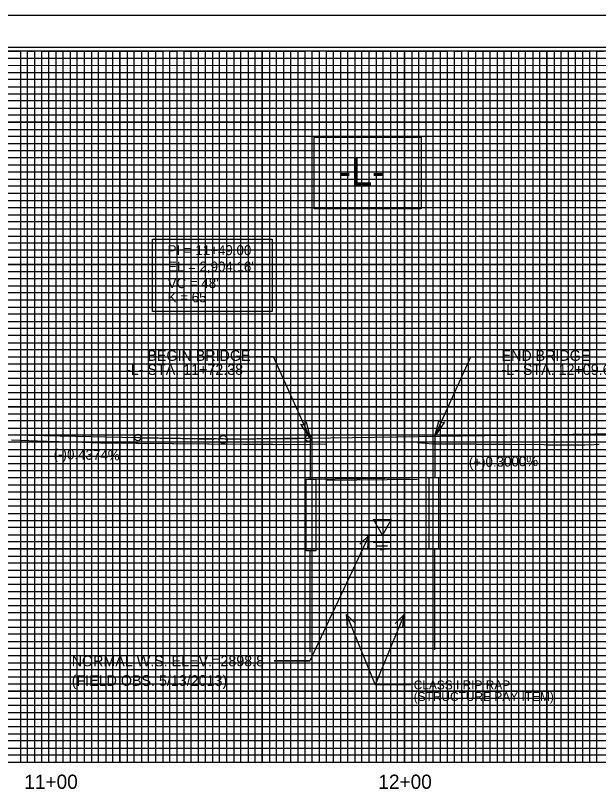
# Model space of a CAD drawing. Extents: x 1191114 to 1192543, y 893004 to 894332.
# Drawn here: x 1191383 to 1191546.9, y 894113.5 to 894332.3 of the extents above; entities that cross this region are included whole.
import ezdxf

# ---------------------------------------------------------------- set-up
doc = ezdxf.new("R2010")
doc.units = 0
for name, color, linetype in [('Default', 7, 'Continuous'), ('Exist Profile Cell', 7, 'Continuous'), ('Exist Vertical Profile Ground Line', 7, 'Continuous'), ('Prop Grid Mask', 7, 'Continuous'), ('Prop PFL Text', 7, 'Continuous'), ('Prop Roadway Bridge', 7, 'Continuous'), ('Prop Terminator CELL', 7, 'Continuous'), ('Prop Vertical Profile Curve Label', 7, 'Continuous'), ('Prop Vertical Profile Grade', 7, 'Continuous'), ('Prop Vertical Profile Grade Label', 7, 'Continuous'), ('Prop VPI Label', 7, 'Continuous'), ('Sheet Cutting Line CELL', 7, 'Continuous'), ('Sheet DOT Grid CELL', 7, 'Continuous'), ('Sheet Layout Profile Border Port 1', 7, 'Continuous'), ('Sheet Plot Border Inside CELL', 7, 'Continuous'), ('Sheet Plot Border Outside CELL', 7, 'Continuous'), ('Sheet Profile CELL', 7, 'Continuous'), ('Sheet Profile Grid Major CELL', 7, 'Continuous'), ('Sheet Profile Grid Middle CELL', 7, 'Continuous'), ('Sheet Profile Grid Minor CELL', 7, 'Continuous'), ('Typical Terminator CELL', 7, 'Continuous')]:
    doc.layers.add(name, color=color, linetype=linetype)

# ---------------------------------------------------------------- blocks, each defined once
blk = doc.blocks.new('Terminator Open Line')
at = {"layer": 'Default'}
blk.add_line((-9, -3.25), (0, 0), dxfattribs=at)
at = {"layer": 'Prop Terminator CELL'}
blk.add_line((-9, 3.3), (0, 0), dxfattribs=at)
blk = doc.blocks.new('TERMINATOR')
at = {"layer": 'Typical Terminator CELL'}
blk.add_lwpolyline([(-0.469, 0.081), (0, 0), (-0.471, -0.083), (-0.411, 0)], close=True, dxfattribs=at)

msp = doc.modelspace()

# ---------------------------------------------------------------- linework, layer by layer
at = {"layer": 'Default'}
for p, q in [((1191470.41, 894201.65), (1191496.05, 894201.95)), ((1191455.77, 894150.79), (1191465.77, 894150.79))]:
    msp.add_line(p, q, dxfattribs=at)
at = {"layer": 'Exist Profile Cell'}
msp.add_line((1191292.39, 894142.3), (1191713, 894142.3), dxfattribs=at)
at = {"layer": 'Exist Vertical Profile Ground Line'}
for points in [[(1191381.86, 894212.98), (1191391.62, 894212.64), (1191391.94, 894212.63), (1191401.84, 894212.28), (1191407.01, 894212.1), (1191407.45, 894212.11), (1191417.01, 894212.02), (1191417.49, 894212.03), (1191427.01, 894211.94), (1191427.53, 894211.95), (1191437.01, 894211.86), (1191437.57, 894211.87), (1191447.01, 894211.79), (1191447.46, 894211.8), (1191454.68, 894211.73), (1191455.32, 894211.74), (1191464.69, 894211.7), (1191466, 894211.74), (1191470.41, 894211.9)], [(1191496.05, 894212.2), (1191500.35, 894211.87), (1191501.99, 894211.9), (1191502.64, 894211.89), (1191511.99, 894211.81), (1191512.64, 894211.8), (1191522.18, 894211.72), (1191531.57, 894211.64), (1191532.17, 894211.62), (1191541.59, 894211.55), (1191542.16, 894211.53), (1191543, 894211.57), (1191545.63, 894211.7), (1191547.04, 894211.77)]]:
    msp.add_lwpolyline(points, dxfattribs=at)
at = {"layer": 'Prop Grid Mask'}
for points in [[(1191467.01, 894298.14), (1191497, 894298.14), (1191497, 894277.95), (1191467.01, 894277.95)], [(1191421.55, 894269.43), (1191455.19, 894269.43), (1191455.19, 894249.11), (1191421.55, 894249.11)]]:
    msp.add_lwpolyline(points, close=True, dxfattribs=at)
at = {"layer": 'Prop PFL Text'}
for p, q in [((1191455.57, 894236.32), (1191450.36, 894236.32)), ((1191465.89, 894213.45), (1191455.57, 894236.32)), ((1191500.89, 894213.98), (1191511.04, 894236.32)), ((1191511.04, 894236.32), (1191516.26, 894236.32)), ((1191482.4, 894186.2), (1191465.77, 894150.79)), ((1191481.44, 894186.2), (1191489.86, 894186.2)), ((1191483.56, 894184.17), (1191488.56, 894184.17)), ((1191484.56, 894183.17), (1191487.56, 894183.17)), ((1191485.56, 894182.17), (1191486.56, 894182.17)), ((1191476.05, 894163.83), (1191484.15, 894144.06)), ((1191492.25, 894163.83), (1191484.15, 894144.06)), ((1191465.77, 894150.79), (1191455.77, 894150.79)), ((1191494.15, 894144.06), (1191484.15, 894144.06))]:
    msp.add_line(p, q, dxfattribs=at)
msp.add_lwpolyline([(1191483.63, 894190.54), (1191488.63, 894190.54), (1191486.13, 894186.2)], close=True, dxfattribs=at)
at = {"layer": 'Prop Roadway Bridge'}
for p, q in [((1191465.89, 894213.45), (1191465.89, 894201.8)), ((1191500.89, 894213.98), (1191500.89, 894202.33)), ((1191467.49, 894201.83), (1191464.74, 894201.78)), ((1191464.74, 894181.78), (1191464.74, 894201.78)), ((1191500.89, 894202.33), (1191465.89, 894201.8)), ((1191467.49, 894181.78), (1191467.49, 894201.83)), ((1191502.04, 894202.34), (1191499.29, 894202.3)), ((1191499.29, 894182.35), (1191499.29, 894202.3)), ((1191502.04, 894182.35), (1191502.04, 894202.34)), ((1191499.29, 894182.35), (1191502.04, 894182.35)), ((1191500.89, 894153.88), (1191500.89, 894182.35)), ((1191467.49, 894181.78), (1191464.74, 894181.78)), ((1191465.89, 894153.23), (1191465.89, 894181.78))]:
    msp.add_line(p, q, dxfattribs=at)
at = {"layer": 'Prop Vertical Profile Curve Label'}
for centre in [(1191417.39, 894213.61), (1191465.39, 894213.44)]:
    msp.add_circle(centre, 0.9, dxfattribs=at)
at = {"layer": 'Prop Vertical Profile Grade'}
for p, q in [((1191342.39, 894215.25), (1191417.39, 894213.61)), ((1191465.39, 894213.44), (1191602.39, 894215.5))]:
    msp.add_line(p, q, dxfattribs=at)
msp.add_spline([(1191417.39, 894213.61), (1191418.35, 894213.59), (1191419.31, 894213.57), (1191420.27, 894213.55), (1191421.23, 894213.53), (1191422.19, 894213.51), (1191423.15, 894213.5), (1191424.11, 894213.48), (1191425.07, 894213.46), (1191426.03, 894213.45), (1191426.99, 894213.43), (1191427.95, 894213.42), (1191428.91, 894213.41), (1191429.87, 894213.4), (1191430.83, 894213.38), (1191431.79, 894213.37), (1191432.75, 894213.36), (1191433.71, 894213.35), (1191434.67, 894213.35), (1191435.63, 894213.34), (1191436.59, 894213.33), (1191437.55, 894213.32), (1191438.51, 894213.32), (1191439.47, 894213.31), (1191440.43, 894213.31), (1191441.39, 894213.31), (1191442.35, 894213.3), (1191443.31, 894213.3), (1191444.27, 894213.3), (1191445.23, 894213.3), (1191446.19, 894213.3), (1191447.15, 894213.3), (1191448.11, 894213.3), (1191449.07, 894213.3), (1191450.03, 894213.3), (1191450.99, 894213.31), (1191451.95, 894213.31), (1191452.91, 894213.32), (1191453.87, 894213.32), (1191454.83, 894213.33), (1191455.79, 894213.34), (1191456.75, 894213.34), (1191457.71, 894213.35), (1191458.67, 894213.36), (1191459.63, 894213.37), (1191460.59, 894213.38), (1191461.55, 894213.39), (1191462.51, 894213.4), (1191463.47, 894213.42), (1191464.43, 894213.43), (1191465.39, 894213.44)], degree=3, dxfattribs=at)
at = {"layer": 'Prop VPI Label'}
for p, q in [((1191417.39, 894213.61), (1191438.64, 894213.14)), ((1191465.39, 894213.44), (1191444.14, 894213.13))]:
    msp.add_line(p, q, dxfattribs=at)
msp.add_circle((1191441.39, 894213.08), 1.1, dxfattribs=at)
at = {"layer": 'Sheet Cutting Line CELL'}
msp.add_line((1191839.19, 894332.3), (1191165.59, 894332.3), dxfattribs=at)
at = {"layer": 'Sheet DOT Grid CELL'}
for p, q in [((1191392.39, 894122.3), (1191392.39, 894322.3)), ((1191412.39, 894122.3), (1191412.39, 894322.3)), ((1191432.39, 894122.3), (1191432.39, 894322.3)), ((1191452.39, 894122.3), (1191452.39, 894322.3)), ((1191472.39, 894122.3), (1191472.39, 894322.3)), ((1191492.39, 894122.3), (1191492.39, 894322.3)), ((1191512.39, 894122.3), (1191512.39, 894322.3)), ((1191532.39, 894122.3), (1191532.39, 894322.3)), ((1191752.37, 894302.3), (1191232.39, 894302.3)), ((1191752.37, 894282.3), (1191232.39, 894282.3)), ((1191832.39, 894262.3), (1191232.39, 894262.3)), ((1191832.39, 894242.3), (1191232.39, 894242.3)), ((1191832.39, 894222.3), (1191232.39, 894222.3)), ((1191832.39, 894202.3), (1191232.39, 894202.3)), ((1191832.39, 894182.3), (1191232.39, 894182.3)), ((1191832.39, 894162.3), (1191232.39, 894162.3)), ((1191832.39, 894142.3), (1191232.39, 894142.3))]:
    msp.add_line(p, q, dxfattribs=at)
at = {"layer": 'Sheet Layout Profile Border Port 1'}
msp.add_lwpolyline([(1191252.39, 894322.3), (1191252.39, 894122.3), (1191812.39, 894122.3), (1191812.39, 894267.28), (1191752.37, 894267.28), (1191752.37, 894322.3)], close=True, dxfattribs=at)
at = {"layer": 'Sheet Plot Border Inside CELL'}
msp.add_lwpolyline([(1191170.79, 893901.28), (1191837.39, 893901.28), (1191837.39, 894323.32), (1191170.79, 894323.32)], close=True, dxfattribs=at)
at = {"layer": 'Sheet Plot Border Outside CELL'}
msp.add_lwpolyline([(1191165.59, 893892.3), (1191839.19, 893892.3), (1191839.19, 894332.3), (1191165.59, 894332.3)], close=True, dxfattribs=at)
at = {"layer": 'Sheet Profile CELL'}
msp.add_line((1191232.39, 894122.3), (1191832.39, 894122.3), dxfattribs=at)
msp.add_lwpolyline([(1191832.39, 894322.3), (1191232.39, 894322.3), (1191232.39, 893902.3), (1191832.39, 893902.3)], close=True, dxfattribs=at)
at = {"layer": 'Sheet Profile Grid Major CELL'}
for points in [[(1191372.39, 894122.3), (1191392.39, 894122.3), (1191392.39, 894322.3), (1191412.39, 894322.3), (1191412.39, 894122.3), (1191432.39, 894122.3), (1191432.39, 894322.3), (1191452.39, 894322.3), (1191452.39, 894122.3), (1191472.39, 894122.3), (1191472.39, 894322.3), (1191492.39, 894322.3), (1191492.39, 894122.3), (1191512.39, 894122.3), (1191512.39, 894322.3), (1191532.39, 894322.3), (1191532.39, 894122.3), (1191552.39, 894122.3)], [(1191232.39, 894302.3), (1191752.39, 894302.3)], [(1191752.39, 894282.3), (1191232.39, 894282.3), (1191232.39, 894262.3), (1191832.39, 894262.3)], [(1191832.39, 894242.3), (1191232.39, 894242.3), (1191232.39, 894222.3), (1191832.39, 894222.3)], [(1191832.39, 894202.3), (1191232.39, 894202.3), (1191232.39, 894182.3), (1191832.39, 894182.3)], [(1191832.39, 894162.3), (1191232.39, 894162.3), (1191232.39, 894162.3), (1191232.39, 894142.3), (1191832.39, 894142.3)]]:
    msp.add_lwpolyline(points, dxfattribs=at)
at = {"layer": 'Sheet Profile Grid Middle CELL'}
msp.add_line((1191232.39, 894312.3), (1191752.37, 894312.3), dxfattribs=at)
for points in [[(1191382.39, 894122.3), (1191402.39, 894122.3), (1191402.39, 894322.3), (1191422.39, 894322.3), (1191422.39, 894122.3), (1191442.39, 894122.3), (1191442.39, 894322.3), (1191462.39, 894322.3), (1191462.39, 894122.3), (1191482.39, 894122.3), (1191482.39, 894122.3), (1191482.39, 894322.3), (1191502.39, 894322.3), (1191502.39, 894122.3), (1191522.39, 894122.3), (1191522.39, 894322.3), (1191542.39, 894322.3), (1191542.39, 894122.3), (1191562.39, 894122.3)], [(1191752.39, 894292.3), (1191232.39, 894292.3), (1191232.39, 894272.3), (1191752.39, 894272.3)], [(1191832.39, 894252.3), (1191232.39, 894252.3), (1191232.39, 894232.3), (1191762.39, 894232.3)], [(1191832.39, 894212.3), (1191232.39, 894212.3), (1191232.39, 894192.3), (1191832.39, 894192.3)], [(1191832.39, 894172.3), (1191232.39, 894172.3), (1191232.39, 894152.3), (1191832.39, 894152.3)], [(1191832.39, 894132.3), (1191232.39, 894132.3)]]:
    msp.add_lwpolyline(points, dxfattribs=at)
at = {"layer": 'Sheet Profile Grid Minor CELL'}
for p, q in [((1191252.39, 894320.3), (1191752.39, 894320.3)), ((1191752.39, 894318.3), (1191252.39, 894318.16)), ((1191252.39, 894316.3), (1191752.39, 894316.3)), ((1191752.37, 894268.3), (1191252.39, 894268.3)), ((1191812.39, 894266.3), (1191252.39, 894266.3)), ((1191812.39, 894264.3), (1191252.39, 894264.3)), ((1191252.39, 894260.3), (1191812.39, 894260.3)), ((1191812.39, 894258.3), (1191252.39, 894258.3)), ((1191252.39, 894256.3), (1191812.39, 894256.3)), ((1191812.39, 894248.3), (1191252.39, 894248.3)), ((1191252.39, 894246.3), (1191812.39, 894246.3)), ((1191812.39, 894238.3), (1191252.39, 894238.3)), ((1191252.39, 894236.3), (1191812.39, 894236.3)), ((1191812.39, 894228.3), (1191252.39, 894228.3)), ((1191252.39, 894226.3), (1191812.39, 894226.3)), ((1191812.39, 894224.3), (1191252.39, 894224.3)), ((1191252.39, 894220.3), (1191812.39, 894220.3)), ((1191812.39, 894218.3), (1191252.39, 894218.3)), ((1191252.39, 894216.3), (1191812.39, 894216.3)), ((1191812.39, 894214.3), (1191252.39, 894214.3)), ((1191252.39, 894210.3), (1191812.39, 894210.3)), ((1191812.39, 894208.3), (1191252.39, 894208.3)), ((1191252.39, 894206.3), (1191812.39, 894206.3)), ((1191812.39, 894204.3), (1191252.39, 894204.3)), ((1191252.39, 894200.3), (1191812.39, 894200.3)), ((1191812.39, 894198.3), (1191252.39, 894198.3)), ((1191252.39, 894196.3), (1191812.39, 894196.3)), ((1191812.39, 894194.3), (1191252.39, 894194.3)), ((1191252.39, 894190.3), (1191812.39, 894190.3)), ((1191812.39, 894188.3), (1191252.39, 894188.3)), ((1191252.39, 894186.3), (1191812.39, 894186.3)), ((1191812.39, 894184.3), (1191252.39, 894184.3)), ((1191252.39, 894180.3), (1191812.39, 894180.3)), ((1191812.39, 894178.3), (1191252.39, 894178.3)), ((1191252.39, 894176.3), (1191812.39, 894176.3)), ((1191812.39, 894174.3), (1191252.39, 894174.3)), ((1191252.39, 894170.3), (1191812.39, 894170.3)), ((1191812.39, 894168.3), (1191252.39, 894168.3)), ((1191812.39, 894166.3), (1191252.39, 894166.3)), ((1191812.39, 894164.3), (1191252.39, 894164.3)), ((1191252.39, 894160.3), (1191812.39, 894160.3)), ((1191812.39, 894158.3), (1191252.39, 894158.3)), ((1191252.39, 894156.3), (1191812.39, 894156.3)), ((1191812.39, 894154.3), (1191252.39, 894154.3)), ((1191252.39, 894150.3), (1191812.39, 894150.3)), ((1191812.39, 894148.3), (1191252.39, 894148.3)), ((1191252.39, 894146.3), (1191812.39, 894146.3)), ((1191812.39, 894144.3), (1191252.39, 894144.3)), ((1191252.39, 894140.3), (1191812.39, 894140.3)), ((1191812.39, 894138.3), (1191252.39, 894138.3)), ((1191252.39, 894136.3), (1191812.39, 894136.3)), ((1191812.39, 894134.3), (1191252.39, 894134.3)), ((1191252.39, 894130.3), (1191812.39, 894130.3)), ((1191812.39, 894128.3), (1191252.39, 894128.3)), ((1191252.39, 894126.3), (1191812.39, 894126.3))]:
    msp.add_line(p, q, dxfattribs=at)
for points in [[(1191380.39, 894322.3), (1191384.39, 894322.3), (1191384.39, 894122.3), (1191386.39, 894122.3), (1191386.39, 894322.3), (1191388.39, 894322.3), (1191388.39, 894122.3), (1191390.39, 894122.3), (1191390.39, 894322.3), (1191394.39, 894322.3), (1191394.39, 894122.3), (1191396.39, 894122.3), (1191396.39, 894322.3), (1191398.39, 894322.3), (1191398.39, 894122.3), (1191400.39, 894122.3), (1191400.39, 894322.3), (1191404.39, 894322.3), (1191404.39, 894122.3), (1191406.39, 894122.3), (1191406.39, 894322.3), (1191408.39, 894322.3), (1191408.39, 894122.3), (1191410.39, 894122.3), (1191410.39, 894322.3), (1191414.39, 894322.3), (1191414.39, 894122.3), (1191416.39, 894122.3), (1191416.39, 894322.3), (1191418.39, 894322.3), (1191418.39, 894122.3), (1191420.39, 894122.3), (1191420.39, 894322.3), (1191424.39, 894322.3), (1191424.39, 894122.3), (1191426.39, 894122.3), (1191426.39, 894322.3), (1191428.39, 894322.3), (1191428.39, 894122.3), (1191430.39, 894122.3), (1191430.39, 894322.3), (1191434.39, 894322.3), (1191434.39, 894122.3), (1191436.39, 894122.3), (1191436.39, 894322.3), (1191438.39, 894322.3), (1191438.39, 894122.3), (1191440.39, 894122.3), (1191440.39, 894322.3), (1191444.39, 894322.3), (1191444.39, 894122.3), (1191446.39, 894122.3), (1191446.39, 894322.3), (1191448.39, 894322.3), (1191448.39, 894122.3), (1191450.39, 894122.3), (1191450.39, 894322.3), (1191454.39, 894322.3), (1191454.39, 894122.3), (1191456.39, 894122.3), (1191456.39, 894322.3), (1191458.39, 894322.3), (1191458.39, 894122.3), (1191460.39, 894122.3), (1191460.39, 894322.3), (1191464.39, 894322.3)], [(1191464.39, 894322.3), (1191464.39, 894122.3), (1191466.39, 894122.3), (1191466.39, 894322.3), (1191468.39, 894322.3), (1191468.39, 894122.3), (1191470.39, 894122.3), (1191470.39, 894322.3), (1191474.39, 894322.3), (1191474.39, 894122.3), (1191476.39, 894122.3), (1191476.39, 894322.3), (1191478.39, 894322.3), (1191478.39, 894122.3), (1191480.39, 894122.3), (1191480.39, 894322.3), (1191484.39, 894322.3), (1191484.39, 894122.3), (1191486.39, 894122.3), (1191486.39, 894322.3), (1191488.39, 894322.3), (1191488.39, 894122.3), (1191490.39, 894122.3), (1191490.39, 894322.3), (1191494.39, 894322.3), (1191494.39, 894122.3), (1191496.39, 894122.3), (1191496.39, 894322.3), (1191498.39, 894322.3), (1191498.39, 894122.3), (1191500.39, 894122.3), (1191500.39, 894322.3), (1191504.39, 894322.3), (1191504.39, 894122.3), (1191506.39, 894122.3), (1191506.39, 894322.3), (1191508.39, 894322.3), (1191508.39, 894122.3), (1191510.39, 894122.3), (1191510.39, 894322.3), (1191514.39, 894322.3), (1191514.39, 894122.3), (1191514.39, 894122.3), (1191516.39, 894122.3), (1191516.39, 894322.3), (1191518.39, 894322.3), (1191518.39, 894122.3), (1191520.39, 894122.3), (1191520.39, 894322.3), (1191524.39, 894322.3), (1191524.39, 894122.3), (1191526.39, 894122.3), (1191526.39, 894322.3), (1191528.39, 894322.3), (1191528.39, 894122.3), (1191530.39, 894122.3), (1191530.39, 894322.3), (1191534.39, 894322.3), (1191534.39, 894122.3), (1191536.39, 894122.3), (1191536.39, 894322.3), (1191538.39, 894322.3), (1191538.39, 894122.3), (1191540.39, 894122.3), (1191540.39, 894322.3), (1191544.39, 894322.3), (1191544.39, 894122.3), (1191546.39, 894122.3), (1191546.39, 894322.3), (1191548.39, 894322.3)], [(1191752.39, 894314.3), (1191252.39, 894314.3), (1191252.39, 894310.3), (1191752.39, 894310.3)], [(1191752.37, 894308.3), (1191252.39, 894308.3), (1191252.39, 894306.3), (1191752.39, 894306.3)], [(1191752.39, 894304.3), (1191252.39, 894304.3), (1191252.39, 894300.3), (1191752.39, 894300.3)], [(1191752.39, 894298.3), (1191252.39, 894298.3), (1191252.39, 894296.3), (1191752.39, 894296.3)], [(1191752.39, 894294.3), (1191252.39, 894294.3), (1191252.39, 894290.3), (1191752.39, 894290.3)], [(1191752.39, 894288.3), (1191252.39, 894288.3), (1191252.39, 894286.3), (1191752.39, 894286.3)], [(1191752.39, 894284.3), (1191252.39, 894284.3), (1191252.39, 894280.3), (1191752.39, 894280.3)], [(1191752.39, 894278.26), (1191252.43, 894278.26), (1191252.43, 894276.3), (1191752.39, 894276.3)], [(1191752.39, 894274.3), (1191252.39, 894274.3), (1191252.39, 894270.3), (1191752.39, 894270.3)], [(1191812.39, 894254.3), (1191252.39, 894254.3), (1191252.39, 894250.3), (1191812.39, 894250.3)], [(1191812.39, 894244.3), (1191252.39, 894244.3), (1191252.39, 894240.3), (1191812.39, 894240.3)], [(1191812.39, 894234.3), (1191252.39, 894234.3), (1191252.39, 894230.3), (1191812.39, 894230.3)], [(1191812.39, 894124.3), (1191252.39, 894124.3)]]:
    msp.add_lwpolyline(points, dxfattribs=at)

# ---------------------------------------------------------------- block references
at = {"layer": 'Prop PFL Text'}
for name, p, xscale, yscale, rotation in [('TERMINATOR', (1191465.89, 894213.45), 10.000000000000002, 10.000000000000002, -65.72425508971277), ('TERMINATOR', (1191465.89, 894213.45), 10.000000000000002, 10.000000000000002, -65.72425508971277), ('TERMINATOR', (1191500.89, 894213.98), 10.000000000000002, 10.000000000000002, -114.44158592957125), ('Terminator Open Line', (1191482.4, 894186.2), 0.3749999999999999, 0.3749999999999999, 64.84399846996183), ('Terminator Open Line', (1191476.05, 894163.83), 0.3749999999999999, -0.3749999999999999, 115.15600153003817), ('Terminator Open Line', (1191492.25, 894163.83), 0.3749999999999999, 0.3749999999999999, 64.84399846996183)]:
    msp.add_blockref(name, p, dxfattribs=dict(at, xscale=xscale, yscale=yscale, rotation=rotation))

# ---------------------------------------------------------------- texts
at = {"layer": 'Default'}
for s, p in [('NORMAL W.S. ELEV.=2898.8', (1191398.82, 894149.29)), ('(FIELD OBS. 5/13/2013)', (1191398.82, 894143.79))]:
    msp.add_text(s, height=3, rotation=360, dxfattribs=at).set_placement(p)
at = {"layer": 'Exist Vertical Profile Ground Line'}
for s, p in [('11+00', (1191385.5, 894114.83)), ('12+00', (1191485.01, 894114.83))]:
    msp.add_text(s, height=4, dxfattribs=at).set_placement(p)
at = {"layer": 'Prop PFL Text'}
for s, height, p in [('BEGIN BRIDGE', 3, (1191420.09, 894235.18)), ('END BRIDGE', 3, (1191519.63, 894235.18)), ('-L- STA. 11+72.38', 3, (1191414.11, 894231.25)), ('-L- STA. 12+09.63', 3, (1191519.63, 894231.25)), ('CLASS I RIP RAP ', 2.5, (1191494.95, 894142.81)), ('(STRUCTURE PAY ITEM)', 2.5, (1191494.95, 894139.54))]:
    msp.add_text(s, height=height, dxfattribs=at).set_placement(p)
at = {"layer": 'Prop Vertical Profile Curve Label'}
for s, height, p in [('-L-', 8, (1191473.74, 894284.5)), ("VC = 48'", 2.8, (1191425.78, 894255.64)), ('K = 65', 2.8, (1191425.78, 894251.66))]:
    msp.add_text(s, height=height, rotation=360, dxfattribs=at).set_placement(p)
at = {"layer": 'Prop Vertical Profile Grade Label'}
for s, rotation, p in [('(-)0.4374%', 358.7472, (1191393.73, 894207.6)), ('(+)0.3000%', 0.8594, (1191510.47, 894205.31))]:
    msp.add_text(s, height=2.8, rotation=rotation, dxfattribs=at).set_placement(p)
at = {"layer": 'Prop VPI Label'}
for s, p in [('PI = 11+49.00', (1191425.78, 894264.92)), ("EL = 2,904.16'", (1191425.88, 894260.31))]:
    msp.add_text(s, height=2.8, rotation=360, dxfattribs=at).set_placement(p)

doc.saveas('drawing.dxf')
